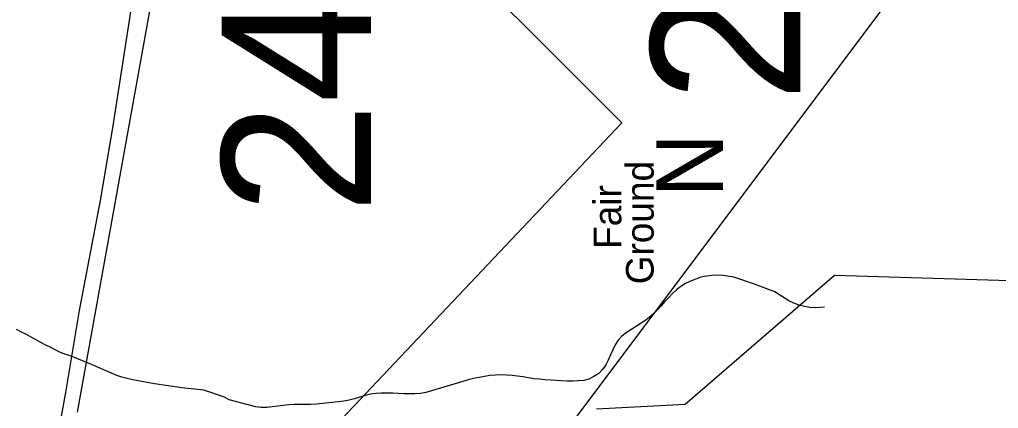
# Model space of a CAD drawing. Extents: x 1373043 to 1375788, y 550128 to 553055.
# Drawn here: x 1373215 to 1373306.4, y 550589.5 to 550625.8 of the extents above; entities that cross this region are included whole.
import ezdxf

# ---------------------------------------------------------------- set-up
doc = ezdxf.new("R2010")
doc.units = 0
for name, color, linetype in [('Old_Level_12', 7, 'Continuous'), ('Old_Level_22', 7, 'Continuous'), ('Old_Level_28', 7, 'Continuous'), ('Old_Level_48', 7, 'Continuous'), ('Old_Level_62', 7, 'Continuous'), ('Prop Dimension', 7, 'Continuous')]:
    doc.layers.add(name, color=color, linetype=linetype)

msp = doc.modelspace()

# ---------------------------------------------------------------- linework, layer by layer
at = {"layer": 'Old_Level_22'}
msp.add_line((1373278.661, 550603.327), (1373278.661, 550603.327), dxfattribs=at)
at = {"layer": 'Old_Level_28'}
for points in [[(1373226.06, 550631.314), (1373225.643, 550628.341), (1373223.711, 550615.873), (1373222.536, 550608.901), (1373220.578, 550598.622), (1373219.35, 550591.16), (1373217.556, 550581.316), (1373216.867, 550573.833), (1373215.589, 550568.429)], [(1373220.412, 550589.14), (1373227.557, 550628.708), (1373228, 550631.121)]]:
    msp.add_lwpolyline(points, dxfattribs=at)
at = {"layer": 'Old_Level_48'}
for p, q in [((1373261.661, 550625.754), (1373249.363, 550637.612)), ((1373271.252, 550616.152), (1373261.661, 550625.754)), ((1373215.374, 550557.12), (1373271.252, 550616.152)), ((1373291.136, 550601.909), (1373277.181, 550589.858)), ((1373319.453, 550601.041), (1373291.136, 550601.909)), ((1373277.181, 550589.858), (1373268.912, 550589.408))]:
    msp.add_line(p, q, dxfattribs=at)
at = {"layer": 'Old_Level_62'}
for points in [[(1373290.198, 550598.952), (1373289.343, 550598.881), (1373288.833, 550598.923), (1373288.32, 550599.014), (1373287.813, 550599.136), (1373287.328, 550599.308), (1373286.87, 550599.537), (1373286.427, 550599.808), (1373285.993, 550600.096), (1373285.554, 550600.373), (1373283.655, 550601.081), (1373281.715, 550601.736), (1373280.716, 550601.894), (1373280.197, 550601.914), (1373279.677, 550601.907), (1373279.167, 550601.846), (1373278.655, 550601.749), (1373278.172, 550601.571), (1373277.69, 550601.368), (1373277.218, 550601.148), (1373276.777, 550600.884), (1373276.38, 550600.561), (1373276.005, 550600.209), (1373275.644, 550599.84), (1373275.288, 550599.459), (1373274.936, 550599.075), (1373274.579, 550598.697), (1373274.211, 550598.332), (1373273.829, 550597.99), (1373273.418, 550597.677), (1373272.989, 550597.389), (1373272.548, 550597.115), (1373272.109, 550596.84), (1373271.681, 550596.549), (1373271.269, 550596.23), (1373270.907, 550595.858), (1373270.646, 550595.419), (1373270.42, 550594.954), (1373270.21, 550594.479), (1373269.995, 550594.005), (1373269.756, 550593.549), (1373269.444, 550593.136), (1373269.1, 550592.745), (1373268.66, 550592.474), (1373268.195, 550592.232), (1373267.702, 550592.102), (1373267.192, 550592.051), (1373266.673, 550592.038), (1373266.15, 550592.044), (1373265.632, 550592.06), (1373265.115, 550592.08), (1373264.6, 550592.115), (1373264.083, 550592.157), (1373263.57, 550592.209), (1373263.056, 550592.264), (1373262.544, 550592.341), (1373262.034, 550592.432), (1373261.524, 550592.513), (1373261.01, 550592.567), (1373260.494, 550592.606), (1373259.975, 550592.622), (1373259.46, 550592.6), (1373258.947, 550592.545), (1373258.435, 550592.471), (1373257.925, 550592.383), (1373257.416, 550592.28), (1373256.912, 550592.164), (1373256.423, 550592.002), (1373254.944, 550591.557), (1373252.953, 550590.979), (1373252.447, 550590.888), (1373251.935, 550590.856), (1373251.42, 550590.846), (1373250.902, 550590.856), (1373250.382, 550590.875), (1373249.862, 550590.895), (1373249.342, 550590.907), (1373248.825, 550590.907), (1373248.312, 550590.885), (1373247.803, 550590.82), (1373247.302, 550590.698), (1373246.805, 550590.546), (1373246.308, 550590.394), (1373245.804, 550590.268), (1373245.295, 550590.171), (1373244.783, 550590.1), (1373242.744, 550589.868), (1373242.229, 550589.848), (1373241.71, 550589.842), (1373241.194, 550589.842), (1373240.675, 550589.838), (1373240.159, 550589.816), (1373239.644, 550589.767), (1373239.13, 550589.706), (1373238.617, 550589.641), (1373238.103, 550589.587), (1373237.588, 550589.564), (1373237.074, 550589.641), (1373236.253, 550589.858)], [(1373236.253, 550589.858), (1373234.605, 550590.291), (1373234.142, 550590.526), (1373232.22, 550591.198), (1373230.168, 550591.408), (1373227.613, 550591.77), (1373227.103, 550591.86), (1373226.594, 550591.954), (1373226.087, 550592.057), (1373225.58, 550592.164), (1373225.077, 550592.283), (1373224.578, 550592.412), (1373224.084, 550592.561), (1373222.666, 550593.171), (1373221.742, 550593.601), (1373219.82, 550594.353), (1373219.328, 550594.508), (1373218.852, 550594.709), (1373218.387, 550594.932), (1373217.926, 550595.164), (1373217.469, 550595.406), (1373217.014, 550595.652), (1373216.56, 550595.9), (1373216.105, 550596.146), (1373215.646, 550596.388), (1373215.186, 550596.621), (1373214.719, 550596.843)]]:
    msp.add_lwpolyline(points, dxfattribs=at)
at = {"layer": 'Prop Dimension'}
msp.add_line((1373307.528, 550642.765), (1373235.141, 550546.227), dxfattribs=at)

# ---------------------------------------------------------------- texts
at = {"layer": 'Old_Level_12'}
for s, p in [('2439', (1373287.921, 550618.104)), ('2481', (1373247.85, 550607.653))]:
    msp.add_text(s, height=13.9517, rotation=90, dxfattribs=at).set_placement(p)
at = {"layer": 'Old_Level_22'}
for s, height, p in [('N', 6.201, (1373280.7, 550609.192)), ('Ground', 2.5837, (1373274.233, 550601.077)), ('Fair', 2.5837, (1373271.213, 550604.382))]:
    msp.add_text(s, height=height, rotation=90.00002, dxfattribs=at).set_placement(p)

doc.saveas('drawing.dxf')
